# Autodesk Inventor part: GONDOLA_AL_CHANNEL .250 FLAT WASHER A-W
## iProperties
Shininess: 64.0
Length Units: 11272
Angle Units: 11279
Time Units: 11290
Mass Units: 11286
Length Display Precision: 3
Angle Display Precision: 2
Compacted: True
Part Number: GONDOLA_AL_CHANNEL .250 FLAT WASHER A-W
Document SubType Name: Modeling
Created: 2004-08
Designer: John Blackburn
Manufacturer: Standard
Standards Organization: Custom
Material: Stainless Steel, Austenitic
Density: 0.0
Volumn: 0.0
Area: 0.0
PropertySet Name: Model Information
Control State: 0
Master: False
Checked Out: False
Author: John Blackburn
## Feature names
1. Base1
